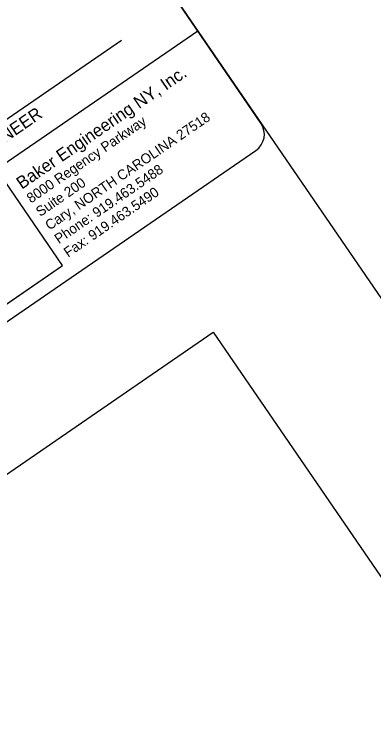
# Model space of a CAD drawing. Extents: x 2385901 to 2398119, y 552503 to 560016.
# Drawn here: x 2397537.9 to 2397661.3, y 559638.4 to 559882.7 of the extents above; entities that cross this region are included whole.
import ezdxf

# ---------------------------------------------------------------- set-up
doc = ezdxf.new("R2010")
doc.units = 0
for name, color, linetype in [('Old_Level_18', 7, 'Continuous'), ('Old_Level_40', 7, 'Continuous'), ('Old_Level_50', 7, 'Continuous')]:
    doc.layers.add(name, color=color, linetype=linetype)

msp = doc.modelspace()

# ---------------------------------------------------------------- linework, layer by layer
at = {"layer": 'Old_Level_18'}
msp.add_line((2397464.58, 559798.16), (2397574.69, 559873.8), dxfattribs=at)
msp.add_lwpolyline([(2397524.57, 559988.17), (2396288.13, 559138.87), (2396882.63, 558273.38), (2398119.05, 559122.67)], close=True, dxfattribs=at)
at = {"layer": 'Old_Level_40'}
for p, q in [((2397622.56, 559845.3), (2397524.57, 559988.17)), ((2397600.94, 559876.86), (2397452.47, 559775.01)), ((2397483.49, 559741.72), (2397620.81, 559835.92))]:
    msp.add_line(p, q, dxfattribs=at)
for points in [[(2397534.94, 559825.02), (2397460.66, 559774.07), (2397480.2, 559745.59), (2397554.47, 559796.56)], [(2397510.6, 559808.34), (2397516.79, 559796.83), (2397517.52, 559793.93), (2397516.85, 559793.76), (2397516.32, 559793.6), (2397515.67, 559793.17), (2397515.17, 559792.68), (2397515.08, 559792.15), (2397515.09, 559791.49), (2397515.27, 559790.94), (2397515.58, 559790.3), (2397516.09, 559789.37), (2397519.55, 559784.3), (2397526.27, 559777.2), (2397554.47, 559796.56), (2397534.94, 559825.02)]]:
    msp.add_lwpolyline(points, close=True, dxfattribs=at)
msp.add_arc((2397617, 559841.48), 6.75, 304.45, 34.45, dxfattribs=at)
at = {"layer": 'Old_Level_50'}
msp.add_lwpolyline([(2396323.89, 559136.9), (2397107.84, 559675.39), (2397182.92, 559566.09), (2397427.9, 559734.37), (2397466.74, 559677.83), (2397606.19, 559773.62), (2398061.84, 559110.28), (2396893.45, 558307.72)], close=True, dxfattribs=at)

# ---------------------------------------------------------------- texts
at = {"layer": 'Old_Level_18'}
msp.add_text('PROJECT ENGINEER', height=4.3018, rotation=34.4849, dxfattribs=at).set_placement((2397499.71, 559814.46))
at = {"layer": 'Old_Level_40'}
for s, height, p in [('Baker Engineering NY, Inc.', 4.2911, (2397540.47, 559822.48)), ('8000 Regency Parkway', 3.433, (2397543.62, 559817.74)), ('Cary, NORTH CAROLINA 27518', 3.433, (2397549.99, 559808.46)), ('Phone: 919.463.5488', 3.433, (2397553.17, 559803.81)), ('Suite 200', 3.433, (2397546.79, 559813.11)), ('Fax: 919.463.5490', 3.433, (2397556.36, 559799.16))]:
    msp.add_text(s, height=height, rotation=34.45, dxfattribs=at).set_placement(p)

doc.saveas('drawing.dxf')
